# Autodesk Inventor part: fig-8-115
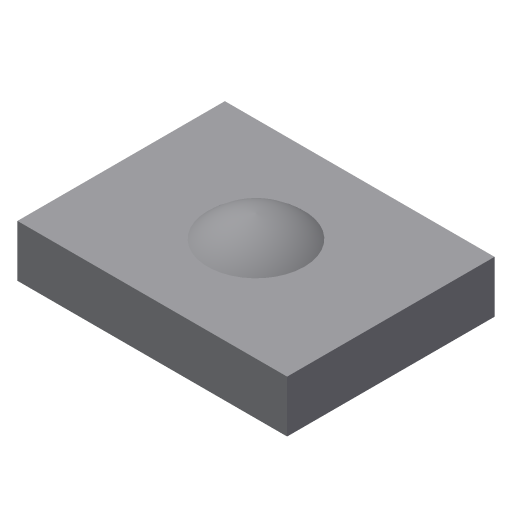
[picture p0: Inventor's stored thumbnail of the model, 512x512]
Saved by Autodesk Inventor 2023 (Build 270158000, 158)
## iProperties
Created: 2009-09
Part Number: fig-8-115
Document SubType Name: Modeling
Designer: Sham
Density: 1 g/cm^3
Material: Generic
Appearance: Default
Author: Sham
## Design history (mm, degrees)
sketch "Sketch1"
  geometry: L1 (-26, 20)-(0, 20); L2 (0, 20)-(0, 0); L3 (0, 0)-(-26, 0); L4 (-26, 0)-(-26, 20)
  constraints: 8 end point, 2 parallel, 1 horizontal, 1 perpendicular
extrude "Extrusion1" new body sketch "Sketch1" distance "d0" = 5; taper "d1" = 0 deg
workplane "Work Plane1"
feature "Sculpt2"
body "Solid1"
sketch "Sketch2"
  geometry: L1 (13, 8)-(13, 5); A1 r 7.517 centre (12.377, -0.349) between (17.658, 5) and (13, 7.142)
  constraints: 2 end point, 2 point on circle, 1 centre point
body "Srf2"
feature "RevolutionSrf2" dims angle "d4" = 90 deg
